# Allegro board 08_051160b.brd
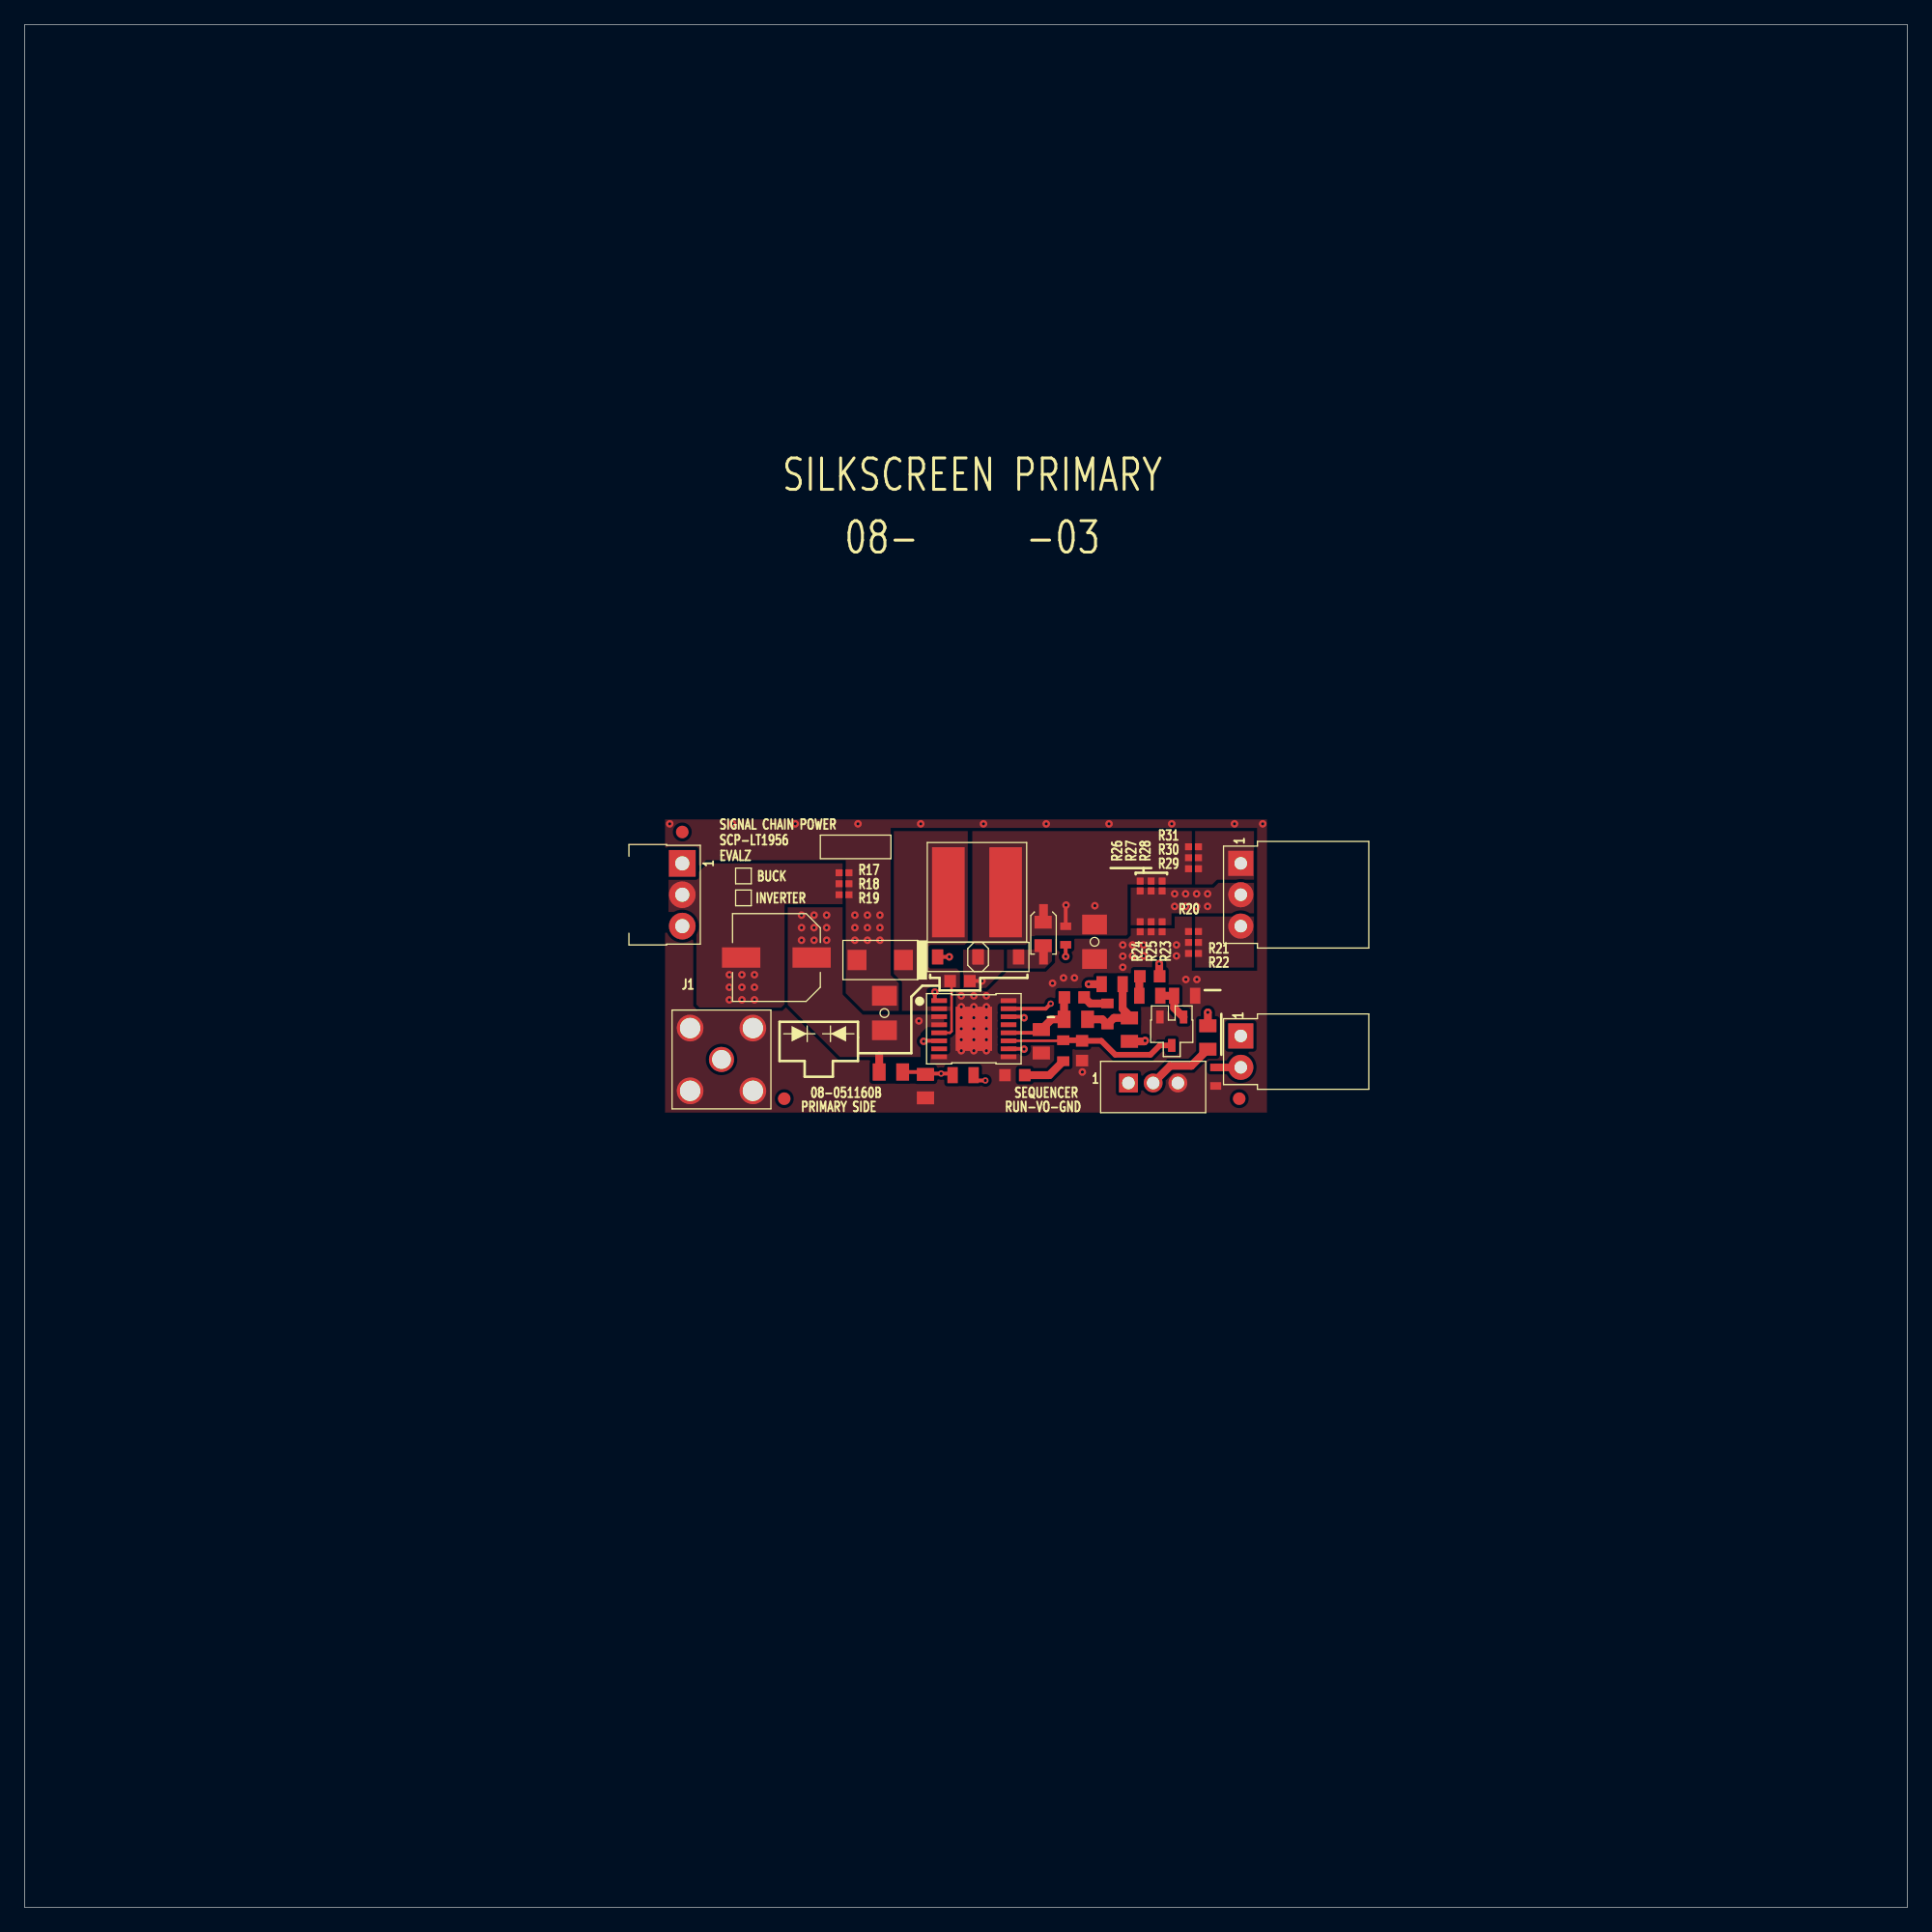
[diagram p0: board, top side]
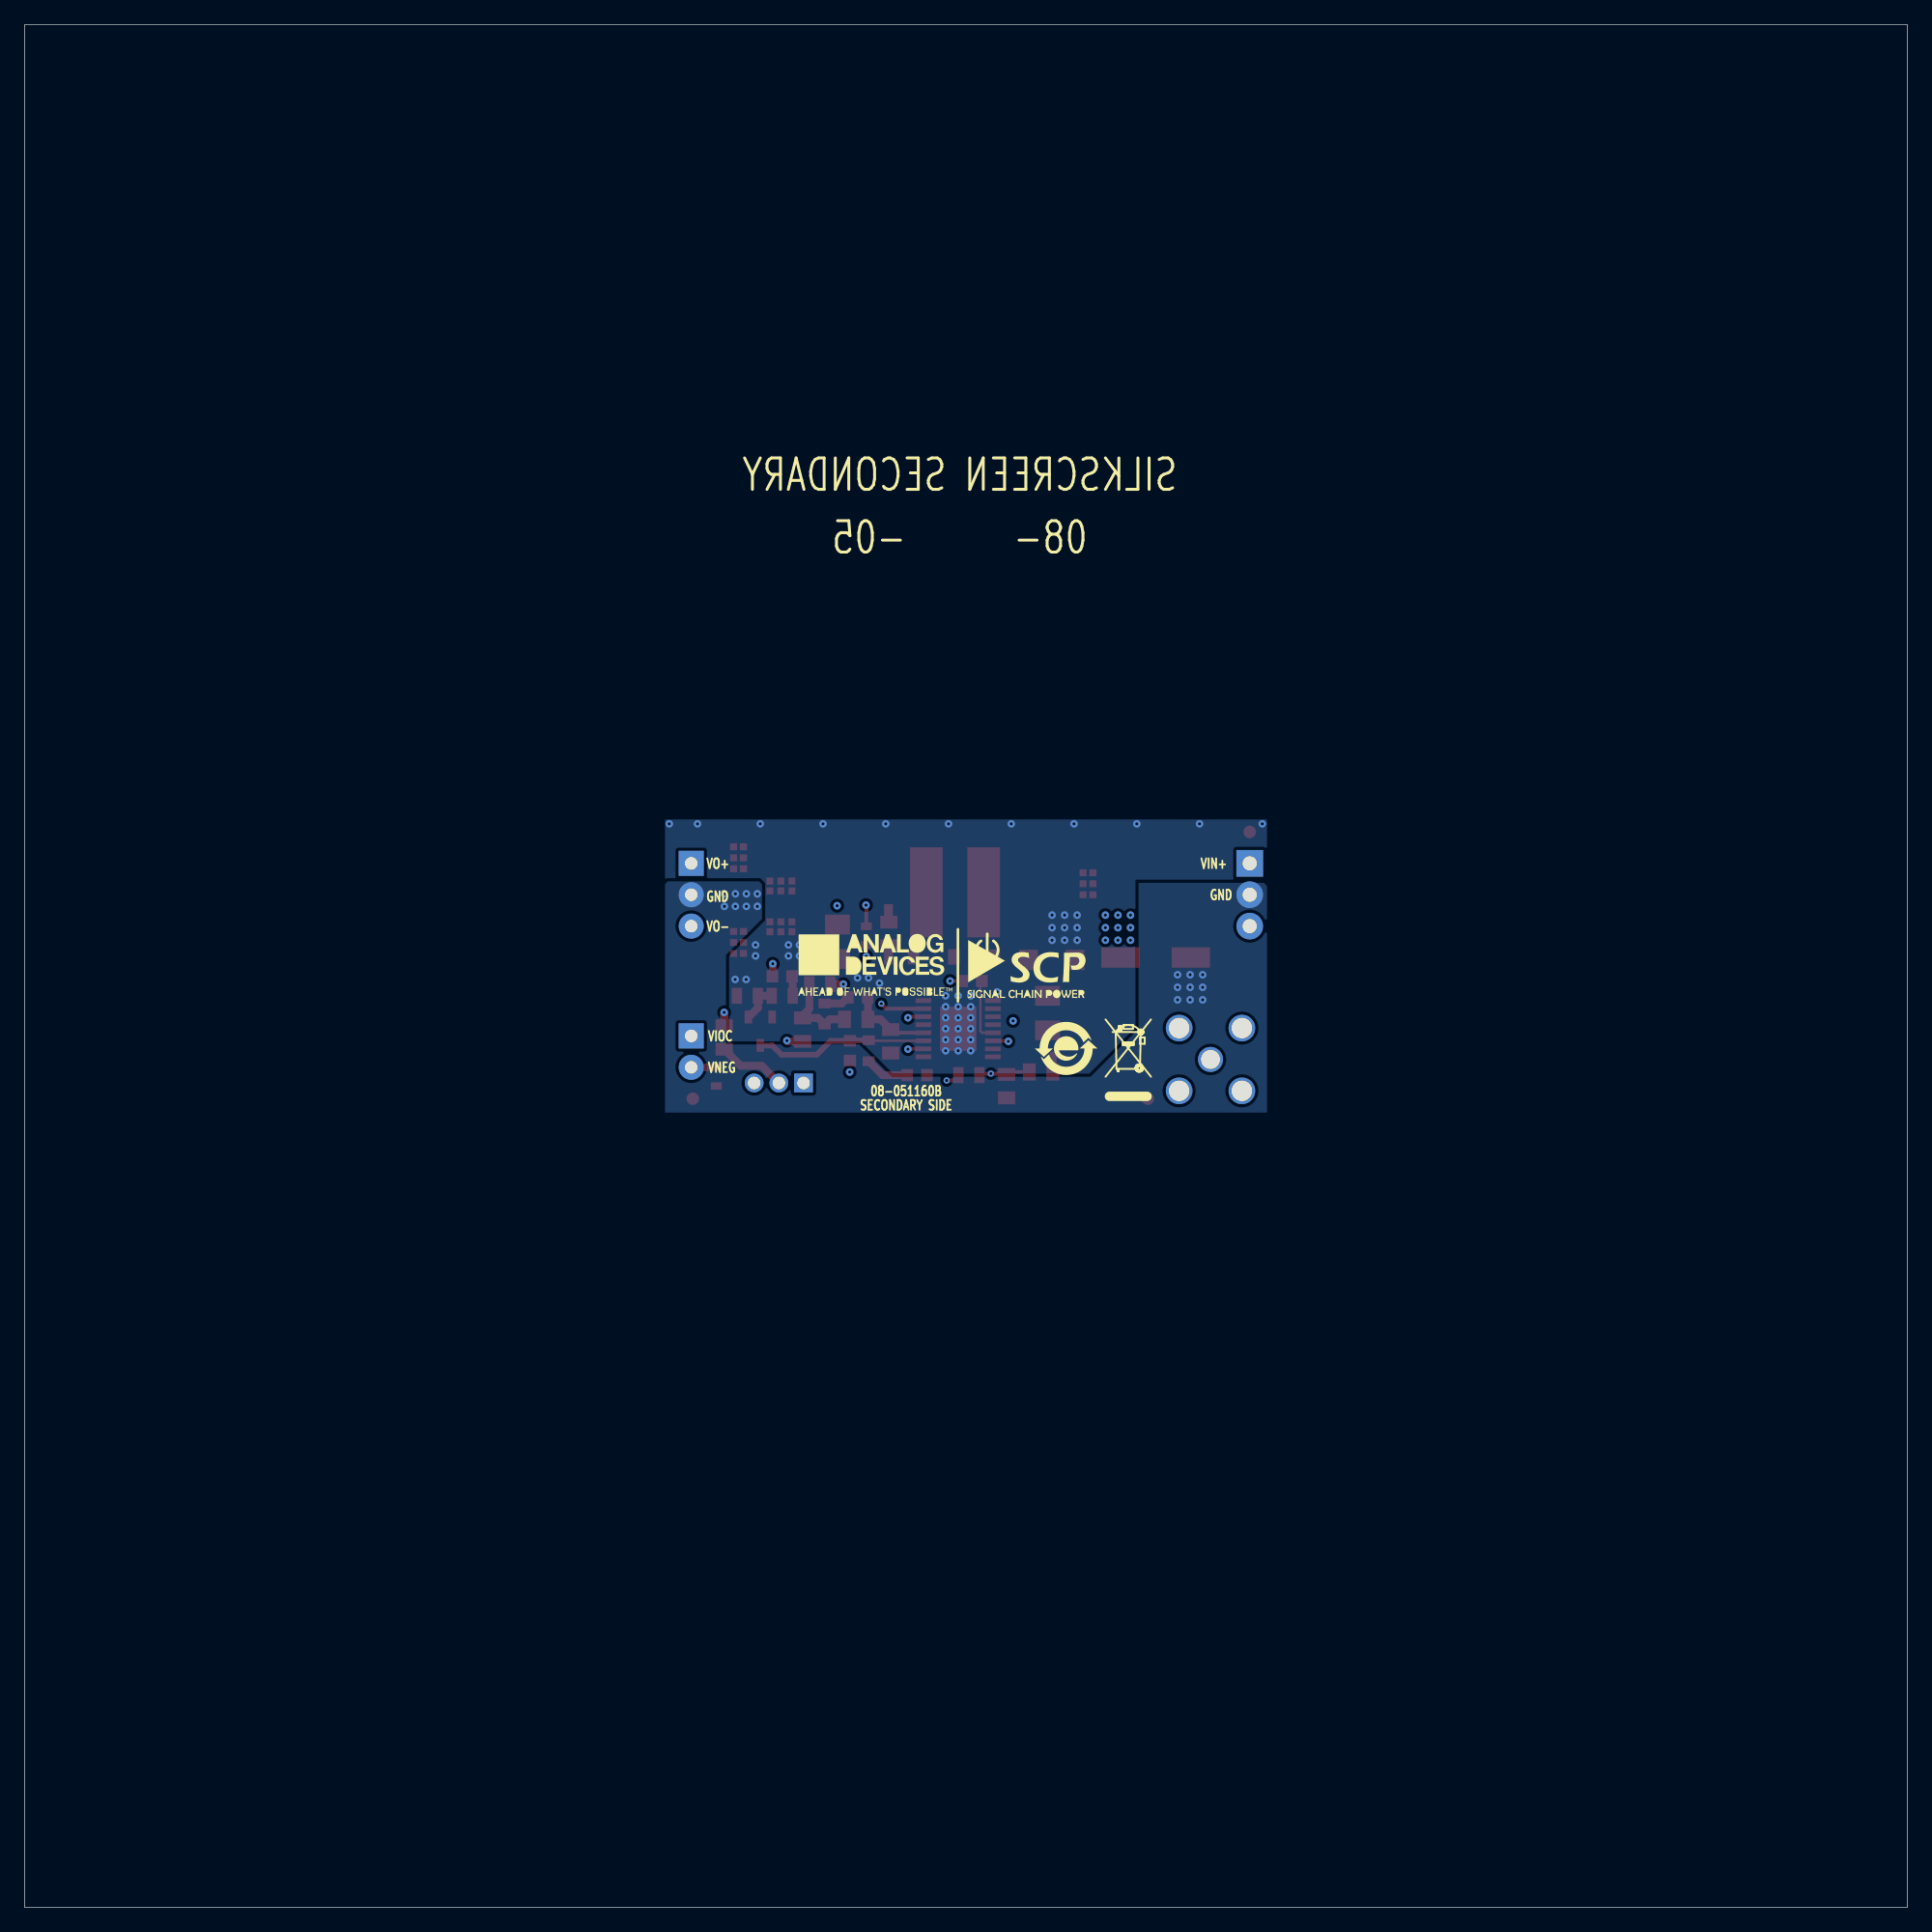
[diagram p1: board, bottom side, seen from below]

Outline 152.4 x 152.4 mm; copper layers: TOP, L2, L3, BOTTOM. Coordinates in mm from the lower left corner of the outline.
Outline path: 0,152.4 152.4,152.4 152.4,0 0,0 0,152.4

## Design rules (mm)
constraint set DEFAULT: min track width 0.203

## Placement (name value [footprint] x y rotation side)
C1  220pF  [C0603]  85.6 69.34 270 top
C2  4700PF  [C0603]  80.16 67.36 0 top
C3  4.7UF  [C1206H71]  69.6 72.39 90 top
C4  0.1UF  [C0603]  75.71 74.98 180 top
C5  22UF  [C1206H71]  86.61 78.16 270 top
C8  TBD0603  [C0603]  84.96 73.66 180 top
C9  TBD0603  [C0603]  91.08 75.37 180 top
C10  100UF  [CPLSMSQ260H315]  60.85 76.89 180 top
D1  VS-10MQ060NTRPBF  [DO214AC_A]  69.26 76.69 180 top
D2  MMSD914T1G  [SOD123-2]  78.82 76.94 0 top
D3  MMSD914T1G  [SOD123-2]  75.54 76.94 180 top
D4  CMHZ5236B  [SOD123-3]  82.47 78.77 270 top
INPUT  PBC03SBAN  [CNTHMHDRRA1X3L300W100H145]  53.23 84.51 270 top
L1  15uH  [LSMSQ264H118_A]  77.09 82.17 0 top
NOREF  -  []  51.2 88.7 0 top
NOREF#2  -  []  51.2 88.7 0 top
NOREF#3  -  []  142.13 171.5 0 top
NOREF#4  -  []  130.7 95.94 0 top
NOREF#5  -  []  101.22 88.77 180 top
NOREF#6  -  []  53.23 84.51 0 top
NOREF#7  -  []  -16.62 14.66 0 top
NOREF#8  -  []  -298.45 -222.25 0 top
NOREF#9  -  []  78 286.44 0 top
NOREF#10  -  []  51.18 88.77 270 top
NOREF#11  -  []  76.71 109.73 0 top
NOREF#12  -  []  51.18 63.63 0 top
NOREF#13  -  [unnamed#2]  61.49 65.46 0 top
NOREF#14  -  [unnamed#2]  98.32 65.46 0 top
NOREF#15  -  []  51.2 88.7 0 top
NOREF#16  -  []  -298.45 -222.25 0 top
NOREF#17  -  []  101.2 63.7 90 top
NOREF#18  -  []  101.22 63.63 90 top
NOREF#19  -  [unnamed#2]  53.23 87.05 0 top
NOREF#20  -  []  -49.64 -72.97 0 top
NOREF#21  -  []  53.23 84.51 0 top
NOREF#22  -  []  63.27 65.33 180 bottom
NOREF#23  -  []  68.09 69.52 180 bottom
NOREF#24  -  []  71.27 76.25 180 bottom
NOREF#25  -  []  83.84 76.25 180 bottom
OUTPUT  PPPC031LGBN-RC  [CNHDRRA1X3H108]  98.44 84.51 270 top
P1  53253-0370  [CNTHMHDR1X3L315W144H224]  89.35 66.73 0 top
Q1  MMBT2222A-7-F  [SOT23_B]  92.86 70.92 180 top
R1  4.7K  [R0603]  84.07 69.34 270 top
R2  15.4K  [R0805#2]  85.09 71.88 180 top
R3  4.99K  [R0805#2]  82.3 70.1 270 top
R4  TBD0603  [R0603]  87.65 72.32 90 top
R5  TBD0805  [R0805#2]  95.78 70.41 90 top
R7  1MEG  [R0805#2]  70.12 67.62 0 top
R8  TBD0805  [R0805#2]  72.92 66.48 270 top
R9  TBD0805  [R0805]  75.97 67.36 180 top
R10  0  [R0603]  84.27 78.67 90 top
R11  0  [R0805#2]  82.44 78.79 90 top
R12  0  [R0603]  96.41 67.24 90 top
R13  0  [R0805]  88.03 74.73 0 top
R14  TBD0805  [R0805#2]  89.43 71.05 270 top
R15  TBD0805  [R0805]  91.08 73.79 0 top
R16  TBD0805  [R0805]  93.9 73.79 0 top
R17  -  [NC0402L]  66.33 83.75 0 top
R18  -  [NC0402L]  66.33 82.86 0 top
R19  -  [NC0402L]  66.33 81.97 0 top
R20  -  [NC0402L]  94.62 78.99 0 top
R21  -  [NC0402L]  94.62 78.11 0 top
R22  -  [NC0402L]  94.62 77.22 0 top
R23  -  [NC0402L]  92.08 79.38 90 top
R24  -  [NC0402L]  90.3 79.38 90 top
R25  -  [NC0402L]  91.19 79.38 90 top
R26  -  [NC0402L]  90.3 82.68 90 top
R27  -  [NC0402L]  91.19 82.68 90 top
R28  -  [NC0402L]  92.08 82.68 90 top
R29  -  [NC0402L]  94.62 84.07 0 top
R30  -  [NC0402L]  94.62 84.96 0 top
R31  -  [NC0402L]  94.62 85.85 0 top
SYNC  5-1814832-1  [CNTYCO1814832]  56.41 68.63 0 top
U1  LT1956EFE#PBF  [TSSOP16_PAD3_58X2_94]  76.84 71.12 270 top
VIOC  PPPC021LGBN-RC  [CNTHFHDRRA1X2L220W335H108]  98.44 70.54 270 top

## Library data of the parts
C1 = CAP: User Part Number: UPN; Tolerance: 5; alternate symbols: (); part number: CAP_SM-220PF,50V,5,E000417,C0603; tolerance: 5
C2 = CAP: User Part Number: UPN; Tolerance: 10; alternate symbols: (); part number: CAP_SM-4700PF,16V,10,E031886,C0603; tolerance: 10
C3 = CAP: Tolerance: 10; User Part Number: UPN; alternate symbols: (); part number: CAP_SM-4.7UF,50V,10,E038262,C1206H71; tolerance: 10
C4 = CAP: User Part Number: UPN; Tolerance: 10; alternate symbols: (); part number: CAP_SM-0.1UF,50V,10,E038267,C0603; tolerance: 10
C5 = CAP: Tolerance: 10; User Part Number: UPN; alternate symbols: (); part number: CAP_SM-22UF,25V,10,E033991,C1206H71; tolerance: 10
C8 C9 = CAP: User Part Number: UPN; alternate symbols: (C0603L, C0603L_ALT); part number: CAP_SM-TBD0603,TBD0603,TBD0603,E000382,C0603
C10 = CAPP: Tolerance: 20; User Part Number: UPN; alternate symbols: (); part number: CAPP_SM-100UF,50V,20,E033839,CPLSMSQ260H315; tolerance: 20
D1 = DIOSCHOTTKY: User Part Number: UPN; Tolerance: N/A; alternate symbols: (); part number: DIOSCHOTTKY_SM-VS-10MQ060NTRPBF,60V,N/A,E033581,DO214AC_A; tolerance: N/A
D2 D3 = DIO: User Part Number: UPN; Tolerance: N/A; alternate symbols: (); part number: DIO_SM-MMSD914T1G,100V,N/A,E033511,SOD123-2; tolerance: N/A
D4 = DIOZNR: Tolerance: 5; User Part Number: UPN; alternate symbols: (); part number: DIOZNR_SM-CMHZ5236B,7.5V,5,E033510,SOD123-3; tolerance: 5
INPUT = CN3P: Tolerance: N/A; User Part Number: UPN; alternate symbols: (CNTHMHDRRA1X3L300W100H145_SCP); part number: CN3P_TH-PBC03SBAN,E034137,CNTHMHDRRA1X3L300W100H145; tolerance: N/A
L1 = IND: Tolerance: 30; User Part Number: UPN; alternate symbols: (); part number: IND_SM-15UH,30,E016696,LSMSQ264H118_A; tolerance: 30
OUTPUT = CN3P: User Part Number: UPN; Tolerance: N/A; alternate symbols: (CNHDRRA1X3H108_SCP); part number: CN3P_TH-PPPC031LGBN-RC,E034111,CNHDRRA1X3H108; tolerance: N/A
P1 = CN3P: Tolerance: N/A; User Part Number: UPN; alternate symbols: (); part number: CN3P_TH-53253-0370,E033940,CNTHMHDR1X3L315W144H224; tolerance: N/A
Q1 = TRANNPN_V2: User Part Number: UPN; Tolerance: N/A; alternate symbols: (); part number: TRANNPN_V2_SM-MMBT2222A-7-F,E033544,SOT23_B; tolerance: N/A
R1 = RES: User Part Number: UPN; Tolerance: 5; alternate symbols: (); part number: RES_SM-4.7K,E031875,1/10W,5,R0603; tolerance: 5
R2 = RES: User Part Number: UPN; Tolerance: 1; alternate symbols: (); part number: RES_SM-15.4K,E033843,1/8W,1,R0805; tolerance: 1
R3 = RES: User Part Number: UPN; Tolerance: 1; alternate symbols: (R0805L); part number: RES_SM-4.99K,E003493,1/8W,1,R0805; tolerance: 1
R4 = RES: User Part Number: UPN; alternate symbols: (R0603L); part number: RES_SM-TBD0603,E004050,TBD0603,TBD0603,R0603
R5 R8 R9 R14-R16 = RES: User Part Number: UPN; alternate symbols: (R0805L); part number: RES_SM-TBD0805,E004051,TBD0805,TBD0805,R0805
R7 = RES: User Part Number: UPN; Tolerance: 5; alternate symbols: (); part number: RES_SM-1MEG,E033749,1/8W,5,R0805; tolerance: 5
R10 R12 = RES: User Part Number: UPN; Tolerance: 5; alternate symbols: (R0603L); part number: RES_SM-0,E006826,1/10W,5,R0603; tolerance: 5
R11 R13 = RES: User Part Number: UPN; Tolerance: N/A; alternate symbols: (R0805L); part number: RES_SM-0,E030875,1/8W,N/A,R0805; tolerance: N/A
R17-R31 = NC2P: User Part Number: UPN; Tolerance: N/A; alternate symbols: (); part number: NC2P_SM-NC0402L,E033984,NC0402L; tolerance: N/A
SYNC = CNBNC5P: Tolerance: N/A; User Part Number: UPN; alternate symbols: (); part number: CNBNC5P_TH-5-1814832-1,E010606,CNTYCO1814832; tolerance: N/A
U1 = ICLT1956: User Part Number: UPN; Tolerance: N/A; alternate symbols: (); part number: ICLT1956_SM-LT1956EFE#PBF,E033520,TSSOP16_PAD3_58X2_94; tolerance: N/A
VIOC = CN2P: Tolerance: N/A; User Part Number: UPN; alternate symbols: (CNTHFHDRRA1X2L220W335H108_SCP); part number: CN2P_TH-PPPC021LGBN-RC,E034113,CNTHFHDRRA1X2L220W335H108; tolerance: N/A

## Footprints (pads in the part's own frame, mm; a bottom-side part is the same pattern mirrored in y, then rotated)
C0603
  rect 0.94x0.991 smd: 1(-0.8,0) 2(0.8,0)
C1206H71
  rect 1.6x2.007 smd: 1(-1.397,0) 2(1.397,0)
CNHDRRA1X3H108
  rect 2.032x2.032 hole 1.016: 1(0,0)
  round 2.032 hole 1.016: 2(2.54,0) 3(5.08,0)
CNTHFHDRRA1X2L220W335H108
  rect 2.032x2.032 hole 1.016: 1(0,0)
  round 2.032 hole 1.016: 2(2.54,0)
CNTHMHDR1X3L315W144H224
  rect 1.524x1.524 hole 1.016: 1(0,0)
  round 1.524 hole 1.016: 2(2,0) 3(4,0)
CNTHMHDRRA1X3L300W100H145
  rect 2.159x2.159 hole 1.143: 1(0,0)
  round 2.159 hole 1.143: 2(2.54,0) 3(5.08,0)
CNTYCO1814832
  round 2.032 hole 1.524: 1(0,0)
  round 2.159 hole 1.651: 2(-2.54,2.54) 3(2.54,2.54) 4(2.54,-2.54) 5(-2.54,-2.54)
CPLSMSQ260H315
  rect 3.099x1.651 smd: N(2.85,0) P(-2.85,0)
DO214AC_A
  rect 1.524x1.651 smd: A(1.88,0) C(-1.88,0)
LSMSQ264H118_A
  rect 2.642x7.29 smd: 1(-2.321,0) 2(2.321,0)
NC0402L
  rect 0.572x0.559 smd: 1(-0.4,0) 2(0.4,0)
R0603
  rect 0.787x0.991 smd: 1(-0.85,0) 2(0.85,0)
R0805
  rect 0.838x1.295 smd: 1(-0.85,0) 2(0.85,0)
R0805#2
  rect 1.041x1.397 smd: 1(-0.95,0) 2(0.95,0)
SOD123-2
  rect 0.914x1.219 smd: A(1.638,0) C(-1.638,0)
SOD123-3
  rect 1.194x0.711 smd: A(1.847,0) C(-1.847,0)
SOT23_B
  rect 0.61x1.041 smd: 1(-0.958,-1.15) 2(0.958,-1.15) 3(0,1.15)
TSSOP16_PAD3_58X2_94
  rect 0.381x1.27 smd: 1(-2.275,-2.81) 2(-1.625,-2.81) 3(-0.975,-2.81) 4(-0.325,-2.81) 5(0.325,-2.81) 6(0.975,-2.81) 7(1.625,-2.81) 8(2.275,-2.81) 9(2.275,2.81) 10(1.625,2.81) 11(0.975,2.81) 12(0.325,2.81) 13(-0.325,2.81) 14(-0.975,2.81) 15(-1.625,2.81) 16(-2.275,2.81)
  rect 3.581x2.946 smd: PAD(0,0)
unnamed#2
  round 1.016 smd: (0,0)

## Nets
GND: C10.N(N2) INPUT.2 OUTPUT.2 R17.1 R18.1 R19.1 R23.2(N2) R24.2(N2) R25.2(N2) R26.1 R27.1 R28.1
RUN: P1.1 R9.1
SYNC: SYNC.1 U1.14
UNNAMED_2_CAP_I14_N2: C2.2(N2) R1.2(N2)
UNNAMED_2_CAP_I17_N1: C1.1 Q1.3 R1.1 U1.11
UNNAMED_2_CAP_I20_N1: C4.1 D2.C D3.C U1.6
UNNAMED_2_CAP_I20_N2: C4.2(N2) D1.C L1.1 U1.2 U1.5
UNNAMED_2_CAP_I24_N1: C5.1 C9.1 D4.C L1.2(N2) R10.2(N2) R11.2(N2) R13.1 R26.2(N2) R27.2(N2) R28.2(N2) R29.1 R30.1 R31.1
UNNAMED_2_CAP_I24_N2: C9.2(N2) R15.1
UNNAMED_2_CAP_I25_N1: C8.1 R4.2(N2)
UNNAMED_2_CAP_I25_N2: C8.2(N2) R2.2(N2) R3.1 U1.12
UNNAMED_2_CN2P_I49_N2: R12.2(N2) VIOC.2(N2)
UNNAMED_2_CN3P_I1_N2: P1.2 R5.1
UNNAMED_2_DIO_I29_P: D2.A(P) D4.A(P) R11.1
UNNAMED_2_ICLT1956_I10_BIAS: R10.1 U1.10
UNNAMED_2_ICLT1956_I10_SHDNN: R7.2(N2) R8.1 R9.2(N2) U1.15
UNNAMED_2_RES_I15_N1: Q1.1 R15.2(N2) R16.1
UNNAMED_2_RES_I26_N1: R2.1 R4.1 R13.2(N2) R14.1
V+: C3.1 C10.P D3.A(P) INPUT.1 R7.1 U1.3 U1.4(VIN)
VIOC: R14.2(N2) VIOC.1
VNEG: C1.2(N2) C2.1 C3.2(N2) C5.2(N2) D1.A(P) P1.3(N3) Q1.2(E) R3.2(N2) R8.2(N2) R12.1 R16.2(N2) R17.2(N2) R18.2(N2) R19.2(N2) R20.1 R21.1 R22.1 R23.1 R24.1 R25.1 SYNC.2 SYNC.3 SYNC.4 SYNC.5(SH4) U1.1 U1.8 U1.9 U1.16 U1.PAD
VO+: OUTPUT.1 R5.2(N2) R29.2(N2) R30.2(N2) R31.2(N2)
VO-: OUTPUT.3(N3) R20.2(N2) R21.2(N2) R22.2(N2)

Pads without a net: INPUT 3; U1 7 13

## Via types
v1: diameter 0.61, hole 0.254, TOP to BOTTOM, 93 vias
v2: diameter 0.508, hole 0.254, TOP to BOTTOM, 3 vias

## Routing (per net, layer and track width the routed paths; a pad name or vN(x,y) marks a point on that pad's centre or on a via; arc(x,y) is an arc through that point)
GND:
  vias: v1(57.04,75.49) v1(57.04,74.48) v1(57.04,73.46) v1(58.06,75.49) v1(58.06,74.48) v1(58.06,73.46) v1(59.07,75.49) v1(59.07,74.48) v1(59.07,73.46) v1(93.09,82.04) v1(93.09,81.03) v1(93.98,82.04) v1(93.98,81.03) v1(94.87,82.04) v1(94.87,81.03) v1(95.76,82.04) v1(95.76,81.03)
RUN: length 12.9
  TOP w0.305: R9.1 76.81,67.15 77.03,66.93 v2(77.77,66.93)
  L3 w0.305: v2(77.77,66.93) 80.87,66.93 81.07,66.73 P1.1
SYNC: length 27.7
  TOP w0.305: U1.14 80.81,72.1 v1(80.9,72.01)
  L3 w0.305: v1(80.9,72.01) 80.9,71.25 78.21,68.56 58.39,68.56 58.31,68.63 SYNC.1
UNNAMED_2_CAP_I14_N2: length 3.6
  TOP w0.635: R1.2 82.95,67.36 C2.2
UNNAMED_2_CAP_I17_N1: length 14
  TOP w0.203: R1.1 84.03,70.14 U1.11
  TOP w0.457: R1.1 85.55,70.19 C1.1 87.16,70.14 88.28,69.02 91.13,69.02 91.88,69.77 Q1.3
UNNAMED_2_CAP_I20_N1: length 10.1
  TOP w0.305: U1.6 72.81,70.14 v1(72.77,70.1) ; C4.1 v1(77.49,74.98)
  L3 w0.305: v1(77.49,74.98) 75.84,74.98 74.95,74.1 74.95,72.28 v1(72.77,70.1)
UNNAMED_2_CAP_I20_N2: length 5.2
  TOP w0.203: U1.5 74.91,70.79 75.03,70.92 75.03,74.86 C4.2
UNNAMED_2_CAP_I24_N1: length 19.1
  TOP w0.305: R10.2 84.27,81.11 v1(84.3,81.13)
  TOP w0.635: C9.1 91.84,75.4 v1(91.84,76.38) ; R13.1 v1(86.13,74.73)
  L3 w0.305: v1(86.13,74.73) 86.13,79.3 v1(84.3,81.13)
  L3 w0.635: v1(91.84,76.38) 91.84,78.03 88.79,81.08 v1(86.63,81.08)
UNNAMED_2_CAP_I24_N2: length 1.6
  TOP w0.635: R15.1 90.23,75.32 C9.2
UNNAMED_2_CAP_I25_N1: length 2.1
  TOP w0.635: R4.2 86.26,73.17 C8.1
UNNAMED_2_CAP_I25_N2: length 6.7
  TOP w0.305: U1.12 82.04,70.79 R3.1
  TOP w0.635: R3.1 83.12,71.88 R2.2 84.14,73.64 C8.2
UNNAMED_2_CN2P_I49_N2: length 2
  TOP w0.61: 98.43,67.99 R12.2
  TOP w0.635: VIOC.2 98.43,67.99
UNNAMED_2_CN3P_I1_N2: length 5.6
  TOP w0.635: P1.2 92.75,68.13 94.44,68.13 R5.1
UNNAMED_2_DIO_I29_P: length 0.9
  TOP w0.203: R11.1 82.44,76.95 D4.A
UNNAMED_2_ICLT1956_I10_BIAS: length 11.1
  TOP w0.305: v1(84.27,76.97) 84.27,76.97 R10.1 ; U1.10 80.87,69.49 v1(80.9,69.47)
  L3 w0.305: v1(80.9,69.47) 80.91,69.47 81.88,70.44 81.88,74.58 v1(84.27,76.97)
UNNAMED_2_ICLT1956_I10_SHDNN: length 20.9
  TOP w0.305: v2(83.06,73.15) 82.65,72.75 U1.15 ; R9.2 74.99,67.49 v2(74.19,67.49) 72.98,67.49 R8.1 72.72,67.62 R7.2
  L3 w0.305: v2(74.19,67.49) 74.42,67.72 80.8,67.72 83.06,69.98 v2(83.06,73.15)
UNNAMED_2_RES_I15_N1: length 3.2
  TOP w0.635: Q1.1 93.78,72.07 93.05,72.81 R16.1 R15.2
UNNAMED_2_RES_I26_N1: length 6.7
  TOP w0.635: R2.1 87.23,71.88 R4.1 88.18,72 R14.1 89.43,72.19 88.88,72.74 R13.2
V+: length 8.5
  TOP w0.305: D3.A 74.84,76.94 v1(74.85,76.94)
  TOP w0.635: R7.1 69.17,68.95
  L3 w0.305: v1(72.39,71.75) 72.39,74.48 v1(74.85,76.94)
  vias: v1(62.88,80.32) v1(62.88,79.3) v1(62.88,78.29) v1(63.9,80.32) v1(63.9,79.3) v1(63.9,78.29) v1(64.92,80.32) v1(64.92,79.3) v1(64.92,78.29)
VIOC: length 9.2
  TOP w0.635: v1(90.7,70.16) 90.64,70.1 R14.2
  L3 w0.635: VIOC.1 91.08,70.54 v1(90.7,70.16)
VNEG: length 1
  TOP w0.305: U1.1 73.79,73.4 73.68,73.51 v1(73.68,74.1)
  vias: v1(52.22,87.71) v1(57.3,87.71) v1(62.38,87.71) v1(67.2,80.32) v1(67.2,79.3) v1(67.2,78.29) v1(67.46,87.71) v1(68.22,80.32) v1(68.22,79.3) v1(68.22,78.29) v1(69.23,80.32) v1(69.23,79.3) v1(69.23,78.29) v1(72.54,87.71) v1(75.82,73.79) v1(75.82,72.9) v1(75.82,72.01) v1(75.82,71.12) v1(75.82,70.23) v1(75.82,69.34) v1(76.84,73.79) v1(76.84,72.9) v1(76.84,72.01) v1(76.84,71.12) v1(76.84,70.23) v1(76.84,69.34) v1(77.62,87.71) v1(77.85,73.79) v1(77.85,72.9) v1(77.85,72.01) v1(77.85,71.12) v1(77.85,70.23) v1(77.85,69.34) v1(82.7,87.71) v1(83.2,74.81) v1(84.09,75.24) v1(84.98,75.24) v1(85.62,67.62) v1(87.78,87.71) v1(88.89,77.91) v1(88.89,76.99) v1(88.89,76.1) v1(89.68,77.91) v1(89.68,77.02) v1(90.57,77.91) v1(90.57,77.02) v1(92.86,87.71) v1(93.24,77.91) v1(93.24,77.02) v1(94,75.11) v1(94.89,75.11) v1(97.94,87.71) v1(100.22,87.71)
VO+: length 14.3
  TOP w0.635: R5.2 v1(95.78,72.44)
  L3 w0.635: OUTPUT.1 97.05,83.11 97.05,73.71 v1(95.78,72.44)

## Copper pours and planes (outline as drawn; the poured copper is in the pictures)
GND on TOP: 52.11,80.57 52.11,83.37 54.12,83.37 55.26,84.51 66.21,84.51 66.21,81.21 61.51,81.21 61.51,73.1 61.23,72.83 54.63,72.83 54.38,73.08 54.38,79.94 53.74,80.57
GND on TOP: 99.51,82.93 99.51,80.47 92.84,80.47 92.84,79.5 89.53,79.5 89.53,82.55 96.27,82.55 96.65,82.93
GND on BOTTOM: 92.96,83.06 100.33,83.06 100.56,82.82 100.56,64.34 51.84,64.34 51.84,82.68 52.09,82.93 62.23,82.93 62.23,71.12 66.12,67.23 82.22,67.23 84.84,69.85 95.63,69.85 95.63,77.09 92.71,80.01 92.71,82.8
GND on L2: 92.96,83.06 100.33,83.06 100.56,82.82 100.56,64.34 51.84,64.34 51.84,82.68 52.09,82.93 62.23,82.93 62.23,71.12 66.75,66.6 86.13,66.6 88.03,68.51 94.29,68.51 95.63,69.85 95.63,77.09 92.71,80.01 92.71,82.8
UNNAMED_2_CAP_I20_N1 on TOP: 79.27,77.52 79.27,75.87 77.82,74.42 75.97,74.42 75.97,77.52
UNNAMED_2_CAP_I20_N2 on TOP: 75.11,72.57 75.11,72.92 73.03,72.92 73.03,74.3 73.15,74.42 75.71,74.42 75.71,75.75 75.46,76 73.3,76 73.17,76.13 73.17,77.78 73.3,77.91 76.09,77.91 76.35,78.16 76.35,87.12 70.36,87.12 70.36,75.57 71.01,74.91 71.01,72.57 71.02,72.57
UNNAMED_2_CAP_I24_N1 on TOP: 94.49,87.12 94.49,82.8 89.28,82.8 89.28,78.78 89.17,78.67 81.81,78.67 81.05,77.91 76.98,77.91 76.71,78.18 76.71,87.12
UNNAMED_2_DIO_I29_P on TOP: 81.73,78.36 83.15,78.36 83.15,76.58 82.57,76 79.52,76 79.52,77.52 81.73,77.52
V+ on TOP: 66.21,73.89 67.84,72.27 68.65,72.26 68.65,72.26 74.42,72.26 74.42,71.25 73.03,71.25 72.52,70.74 72.52,68.83 66.26,68.83 66.26,68.84 65.98,68.84 61.77,73.05 61.77,80.95 66.21,80.95
V+ on L3: 52.34,87.05 52.34,82.99 59.71,82.99 61.74,80.95 61.74,77.52 66.19,77.52 66.19,87.05
VNEG on TOP: 51.84,88.06 100.56,88.06 100.56,64.34 51.84,64.34 ; 13 cut-outs
VNEG on BOTTOM, L2, L3: 51.84,88.06 100.56,88.06 100.56,64.34 51.84,64.34
VO+ on TOP: 94.74,87.12 99.51,87.12 99.51,83.19 96.52,83.19 96.14,82.8 94.74,82.8
VO- on TOP: 99.51,76.07 94.74,76.07 94.74,80.21 99.51,80.21

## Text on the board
Ref Des/Silkscreen Bottom: GND | VIN+ | VIOC | VNEG | VO+ | VO- | 08-051160B | SECONDARY SIDE
User.Comments: 5.    INSTALL SOLDER BLOB USING THE TABLE BELOW (SEE DETAIL A) | AND PLACE MARK ON TICK BOX IN THE PRIMARY SIDE | SCALE FACTOR: 1:4 | BOM | 05-051160-02-b | 05-051160-01-b | DETAIL A | PARTS | R20, R21, R22, R26, R27, R28 | R17, R18, R19, R23, R24, R25, R29, R30, R31 | TICK BOX | BUCK | INVERTER
Ref Des/Silkscreen Top: J1 | SIGNAL CHAIN POWER | SCP-LT1956 | EVALZ | INVERTER | BUCK | PRIMARY SIDE | 08-051160B | RUN-VO-GND | SEQUENCER
PAGE_OUTLINE: B | AS PER ECR-086386 | 07MAY19 | J. VIERNES
DIMENSION: REF | SEE FAB NOTE 15 | DIA MAX
User.15: 15.    THRU VIAS TO BE FILLED WITH SOLDERMASK.
User.17: L2 | 08-      -07
User.18: L3 | 08-      -08
User.45: FIGURE | SIZE | 10.0 | 40.0 | 45.0 | 60.0 | 65.0 | PLATED | FINISHED HOLES IN MILS | ALL UNITS ARE IN MILS | QTY | 96 | 8 | 3 | 1 | 4 | TOLERANCE/NOTES
